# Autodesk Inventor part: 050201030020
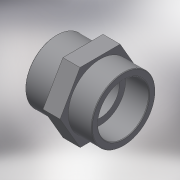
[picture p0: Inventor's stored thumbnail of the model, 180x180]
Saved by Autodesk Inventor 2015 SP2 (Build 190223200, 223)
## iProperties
Created: 2017-10
Part Number: 050201030020
Material: Generic
Description: PLASSON THREADED REDUCER PVC 3"-2"F
Document SubType Name: Modeling
Designer: KIM
Density: 1 g/cm^3
Appearance: Default
Author: KIM
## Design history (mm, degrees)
derived "050201.ipt"
feature "Solid1::050201.ipt"
tag "TaggingFeature1"
body "Solid1"
other parameters: "d0" = 72, "d1" = 56.656, "d2" = 95, "d4" = 45.3248, "d5" = 19, "d6" = 34, "d8" = 87.884, "d10" = 34, "d13" = 0, "d14" = 0.87884, "d16" = 70.3072, "d17" = 79.3184, "R_" = 87.884, "C_" = 95, "lt_" = 34, "H_" = 72, "G_" = 56.656, "lt_1" = 19
